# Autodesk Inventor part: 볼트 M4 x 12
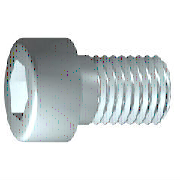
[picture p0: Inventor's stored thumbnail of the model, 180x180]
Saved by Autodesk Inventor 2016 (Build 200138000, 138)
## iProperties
IsCustomPart: 1
Created: 2012-02
Part Number: 볼트 M4 x 12
Material: 스테인리스강
Description: 6각 소켓 머리 캡 나사
Document SubType Name: Modeling
Standard: ISO 4762
Designer: mduedu
Standard Revision: Fourth edition 2004-03-01
Standards Organization: ISO
Language: ko-KR
Size Designation: M4 x 8
Categories: <MemberInstance><Categories><Category DisplayName="조임쇠" InternalName="e4da775c-781d-43d5-af7c-5136215cf5a6" Mnemonic="FSTN"><Category DisplayName="볼트" InternalN
Density: 7.75 g/cm^3
Appearance: 반광택
Author: mduedu
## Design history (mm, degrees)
sketch "스케치1"
  geometry: L1 (-1, 0)-(12, 0); L2 (12, 0)-(12, 2); L3 (12, 2)-(1.75, 2); L4 (1.75, 2)-(1.32, 2); L5 (1.32, 2)-(0, 2); L6 (0, 2)-(0, 3.5); L7 (0, 3.5)-(-4, 3.5); L8 (-4, 3.5)-(-4, 1.732); L9 (-4, 1.732)-(-2, 1.732); L10 (-2, 1.732)-(-1, 0); L11 (-7.2, 0)-(15.2, 0) reference; L12 (0, -0.7)-(0, 4.2) reference; L13 (1.75, 2)-(0, 2)
  constraints: 22 end point, 6 parallel, 2 collinear, 2 perpendicular, 1 horizontal, 1 point on line
  dimensions: "d1" = 10.25 distance from line of L3.end L2 (= GEL); "d2" = 0.42952 distance of L4.end L3.end (computed from GAL); "d3" = 4 distance between parallel lines of L8 L6 (= KOH); "d4" = 2 distance of L8.end L9.end (= INTI); "d5" = 60 deg angle of L10 L1; "d6" = 4 diameter of L3 L1 (= GD); "d7" = 4 diameter of L5 L1 (= BDM); "d8" = 3.4641 diameter of L9 L1 (= 1.1547 x SW); "d9" = 7 diameter of L7 L1 (= KOD); "d26" = 12 distance between parallel lines of L12 L2 (= NLG)
revolve "본체" sketch "스케치1" stored, may be unused: angle "d10" = 90 deg
sketch "스케치2"
  geometry: L1 (0, -4.9)-(0, 4.9) reference; L2 (-4.9, 0)-(4.9, 0) reference; L3 (1.732, 0)-(0.866, -1.5); L4 (0.866, -1.5)-(-0.866, -1.5); L5 (-0.866, -1.5)-(-1.732, 0); L6 (-1.732, 0)-(-0.866, 1.5); L7 (-0.866, 1.5)-(0.866, 1.5); L8 (0.866, 1.5)-(1.732, 0); 2 further points
  constraints: 12 end point, 1 coincident, 1 horizontal alignment, 1 point on line, 12 other
extrude "슬롯" join sketch "스케치2" stored distance "d11" = 10; taper "d12" = 0 deg
workplane "Work Plane1"
fillet "Fillet2" dims "d30" = 0.1 (= R)
body "Solid1"
fillet "모깎기1" dims "d17" = 0.4 (= RR)
feature "스레드" dims "d13" = 10.25 (= GEL), "d14" = 0
chamfer "모따기1" distance "d15" = 0.42941 (= -0.5 x SPD + 0.5 x GD); stored, may be unused: second distance "d16" = 0.42941 (= GUL), angle "d27" = 45 deg
other parameters: "GD" = 4 [user parameter; used in 2 equation terms], "NLG" = 12 [user parameter; used in 1 equation term], "GEL" = 10.25 [user parameter; used in 2 equation terms], "KOD" = 7 [user parameter; used in 1 equation term], "KOH" = 4 [user parameter; used in 1 equation term], "INTI" = 2 [user parameter; used in 1 equation term], "GAL" = 0.42941 (= 0.61345 x PTC) [user parameter; used in 1 equation term], "GUL" = 0.42941 (= 0.61345 x PTC) [user parameter; used in 1 equation term], "BDM" = 4 (= NND) [user parameter; used in 1 equation term], "SW" = 3 [user parameter; used in 2 equation terms], "RR" = 0.4 [user parameter; used in 1 equation term], "SPD" = 3.14117 (= NND - 1.2269 x PTC) [user parameter; used in 1 equation term], "d19" = 0, "d28" = 0, "d29" = 0, "R" = 0.1 [user parameter; used in 1 equation term], "TOA" = 30 deg [user parameter], "GD1" = 3.14117 (= THREADDIA - 1.2269 x PTC) [user parameter], "THREADDIA" = 4 [user parameter; used in 1 equation term], "FAWI" = 45 deg [user parameter], "TPU" = 14.28571 (computed from PTC) [user parameter], "PTC" = 0.7 [user parameter; used in 5 equation terms], "NND" = 4 [user parameter; used in 2 equation terms], "E0" = 3.465 (= 1.155 x SW) [user parameter]
